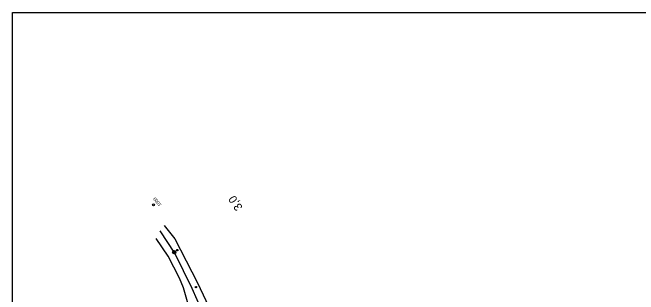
# Model space of a CAD drawing. Extents: x -728800 to -728100, y -1073200 to -1072700.
# Drawn here: x -728800 to -728342.2, y -1072906.2 to -1072700 of the extents above; entities that cross this region are included whole.
import ezdxf

# ---------------------------------------------------------------- set-up
doc = ezdxf.new("R2010")
doc.units = 0
for name, color, linetype in [('A1_OBVOD Spravy železnic', 7, 'Continuous'), ('B4_Bodové pole', 7, 'Continuous'), ('B6_JŽM', 7, 'Continuous')]:
    doc.layers.add(name, color=color, linetype=linetype)

msp = doc.modelspace()

# ---------------------------------------------------------------- linework, layer by layer
at = {"layer": 'A1_OBVOD Spravy železnic'}
for points in [[(-728689.16, -1072855.88), (-728681.24, -1072865.51), (-728664.64, -1072897.67), (-728648.31, -1072932.44)], [(-728671.52, -1072913.23), (-728674.84, -1072901.32), (-728677.82, -1072894.3), (-728686.27, -1072878.28), (-728694.86, -1072865.19)]]:
    msp.add_lwpolyline(points, dxfattribs=at)
at = {"layer": 'B4_Bodové pole'}
msp.add_line((-728696.89, -1072840.77), (-728696.95, -1072840.69), dxfattribs=at)
msp.add_circle((-728696.92, -1072840.73), 0.756, dxfattribs=at)
at = {"layer": 'B6_JŽM'}
for p, q in [((-728679.32, -1072873.78), (-728679.38, -1072873.7)), ((-728665.89, -1072900.84), (-728665.79, -1072900.84))]:
    msp.add_line(p, q, dxfattribs=at)
for points in [[(-728800, -1073200), (-728800, -1072700), (-728100, -1072700), (-728100, -1073200), (-728800, -1073200)], [(-728300.81, -1073024.35), (-728320.8, -1073026.91), (-728374.01, -1073033.72), (-728429.1, -1073040.75), (-728461.93, -1073044.27), (-728481.2, -1073044.81), (-728499.35, -1073043.65), (-728506.01, -1073042.74), (-728514.57, -1073041.33), (-728535.85, -1073036), (-728561.35, -1073026.11), (-728583.96, -1073013.52), (-728603.76, -1072998.89), (-728619.19, -1072984.42), (-728634.19, -1072966.82), (-728646.08, -1072949.19), (-728656.18, -1072930.07), (-728664.99, -1072910.23), (-728668.63, -1072901.81), (-728681.25, -1072876.02), (-728691.89, -1072859.66)]]:
    msp.add_lwpolyline(points, dxfattribs=at)
for centre, radius in [((-728681.73, -1072875.28), 1.25), ((-728679.35, -1072873.74), 0.5), ((-728681.73, -1072875.28), 0.752), ((-728665.84, -1072900.84), 0.499)]:
    msp.add_circle(centre, radius, dxfattribs=at)

# ---------------------------------------------------------------- texts
at = {"layer": 'B4_Bodové pole'}
msp.add_text('1009', height=2.4, rotation=130.1205, dxfattribs=at).set_placement((-728690.86, -1072840.52))
at = {"layer": 'B6_JŽM'}
msp.add_text('3,0', height=6, rotation=123.0351, dxfattribs=at).set_placement((-728631.43, -1072842.57))

doc.saveas('drawing.dxf')
